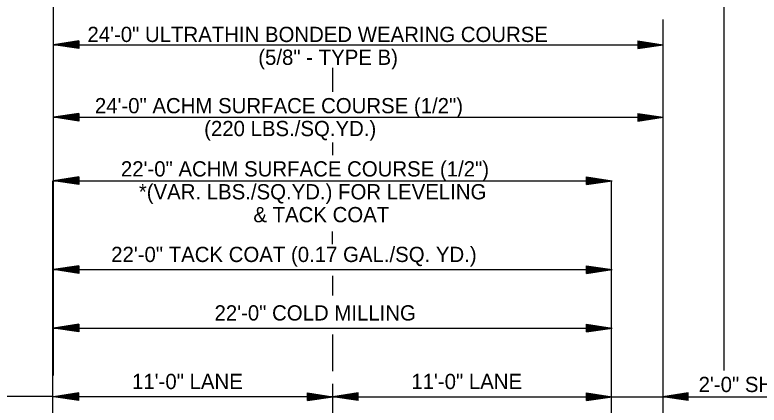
# Model space of a CAD drawing. Extents: x 2263886 to 2266026, y -3122850 to -3121850.
# Drawn here: x 2265384.71 to 2265414.02, y -3122478.48 to -3122463.12 of the extents above; entities that cross this region are included whole.
import ezdxf

# ---------------------------------------------------------------- set-up
doc = ezdxf.new("R2010")
doc.units = 0
doc.layers.add('R_Border Prem', color=7, linetype='Continuous')

msp = doc.modelspace()

# ---------------------------------------------------------------- linework, layer by layer
at = {"layer": 'R_Border Prem'}
for p, q in [((2265386.232, -3122477.321), (2265386.232, -3122460.397)), ((2265412.645, -3122477.115), (2265412.645, -3122460.346)), ((2265410.25, -3122482.649), (2265410.25, -3122463.3)), ((2265387.232, -3122464.15), (2265386.232, -3122464.3)), ((2265386.232, -3122464.3), (2265410.25, -3122464.3)), ((2265387.232, -3122464.45), (2265386.232, -3122464.3)), ((2265387.232, -3122464.175), (2265386.399, -3122464.3)), ((2265387.232, -3122464.425), (2265386.399, -3122464.3)), ((2265387.232, -3122464.201), (2265386.571, -3122464.3)), ((2265387.232, -3122464.4), (2265386.571, -3122464.3)), ((2265387.232, -3122464.226), (2265386.738, -3122464.3)), ((2265387.232, -3122464.375), (2265386.738, -3122464.3)), ((2265387.232, -3122464.252), (2265386.907, -3122464.3)), ((2265387.232, -3122464.349), (2265386.907, -3122464.3)), ((2265387.232, -3122464.277), (2265387.074, -3122464.3)), ((2265387.232, -3122464.324), (2265387.074, -3122464.3)), ((2265387.232, -3122464.15), (2265387.232, -3122464.45)), ((2265409.25, -3122464.15), (2265410.25, -3122464.3)), ((2265409.25, -3122464.15), (2265409.25, -3122464.45)), ((2265409.25, -3122464.175), (2265410.083, -3122464.3)), ((2265409.25, -3122464.201), (2265409.911, -3122464.3)), ((2265409.25, -3122464.226), (2265409.745, -3122464.3)), ((2265409.25, -3122464.252), (2265409.575, -3122464.3)), ((2265409.25, -3122464.277), (2265409.408, -3122464.3)), ((2265409.25, -3122464.45), (2265410.25, -3122464.3)), ((2265409.25, -3122464.349), (2265409.575, -3122464.3)), ((2265409.25, -3122464.4), (2265409.911, -3122464.3)), ((2265409.25, -3122464.425), (2265410.083, -3122464.3)), ((2265409.25, -3122464.375), (2265409.745, -3122464.3)), ((2265409.25, -3122464.324), (2265409.408, -3122464.3)), ((2265397.232, -3122466.149), (2265397.232, -3122465.205)), ((2265387.232, -3122466.999), (2265386.232, -3122467.149)), ((2265387.232, -3122467.024), (2265386.399, -3122467.149)), ((2265387.232, -3122466.999), (2265387.232, -3122467.299)), ((2265409.25, -3122466.999), (2265410.25, -3122467.149)), ((2265409.25, -3122466.999), (2265409.25, -3122467.299)), ((2265409.25, -3122467.024), (2265410.083, -3122467.149)), ((2265386.232, -3122467.149), (2265410.25, -3122467.149)), ((2265387.232, -3122467.299), (2265386.232, -3122467.149)), ((2265387.232, -3122467.274), (2265386.399, -3122467.149)), ((2265387.232, -3122467.05), (2265386.571, -3122467.149)), ((2265387.232, -3122467.249), (2265386.571, -3122467.149)), ((2265387.232, -3122467.075), (2265386.738, -3122467.149)), ((2265387.232, -3122467.224), (2265386.738, -3122467.149)), ((2265387.232, -3122467.101), (2265386.907, -3122467.149)), ((2265387.232, -3122467.198), (2265386.907, -3122467.149)), ((2265387.232, -3122467.126), (2265387.074, -3122467.149)), ((2265387.232, -3122467.173), (2265387.074, -3122467.149)), ((2265409.25, -3122467.05), (2265409.911, -3122467.149)), ((2265409.25, -3122467.075), (2265409.745, -3122467.149)), ((2265409.25, -3122467.101), (2265409.575, -3122467.149)), ((2265409.25, -3122467.126), (2265409.408, -3122467.149)), ((2265409.25, -3122467.299), (2265410.25, -3122467.149)), ((2265409.25, -3122467.198), (2265409.575, -3122467.149)), ((2265409.25, -3122467.249), (2265409.911, -3122467.149)), ((2265409.25, -3122467.274), (2265410.083, -3122467.149)), ((2265409.25, -3122467.224), (2265409.745, -3122467.149)), ((2265409.25, -3122467.173), (2265409.408, -3122467.149)), ((2265397.232, -3122468.649), (2265397.232, -3122468.149)), ((2265386.212, -3122469.649), (2265408.232, -3122469.649)), ((2265386.212, -3122482.649), (2265386.212, -3122469.649)), ((2265387.232, -3122469.499), (2265386.232, -3122469.649)), ((2265387.232, -3122469.799), (2265386.232, -3122469.649)), ((2265387.232, -3122469.524), (2265386.399, -3122469.649)), ((2265387.232, -3122469.774), (2265386.399, -3122469.649)), ((2265387.232, -3122469.55), (2265386.571, -3122469.649)), ((2265387.232, -3122469.749), (2265386.571, -3122469.649)), ((2265387.232, -3122469.575), (2265386.738, -3122469.649)), ((2265387.232, -3122469.724), (2265386.738, -3122469.649)), ((2265387.232, -3122469.601), (2265386.907, -3122469.649)), ((2265387.232, -3122469.698), (2265386.907, -3122469.649)), ((2265387.232, -3122469.626), (2265387.074, -3122469.649)), ((2265387.232, -3122469.673), (2265387.074, -3122469.649)), ((2265387.232, -3122469.499), (2265387.232, -3122469.799)), ((2265407.232, -3122469.499), (2265408.232, -3122469.649)), ((2265407.232, -3122469.799), (2265407.232, -3122469.499)), ((2265407.232, -3122469.524), (2265408.065, -3122469.649)), ((2265407.232, -3122469.55), (2265407.893, -3122469.649)), ((2265407.232, -3122469.575), (2265407.727, -3122469.649)), ((2265407.232, -3122469.6), (2265407.557, -3122469.649)), ((2265407.232, -3122469.626), (2265407.39, -3122469.649)), ((2265407.232, -3122469.799), (2265408.232, -3122469.649)), ((2265407.232, -3122469.698), (2265407.557, -3122469.649)), ((2265407.232, -3122469.749), (2265407.893, -3122469.649)), ((2265407.232, -3122469.774), (2265408.065, -3122469.649)), ((2265407.232, -3122469.724), (2265407.727, -3122469.649)), ((2265407.232, -3122469.673), (2265407.39, -3122469.649)), ((2265408.208, -3122482.649), (2265408.208, -3122469.649)), ((2265397.229, -3122472.149), (2265397.229, -3122471.649)), ((2265387.232, -3122472.999), (2265386.232, -3122473.149)), ((2265386.232, -3122473.149), (2265408.232, -3122473.149)), ((2265387.232, -3122473.299), (2265386.232, -3122473.149)), ((2265387.232, -3122473.024), (2265386.399, -3122473.149)), ((2265387.232, -3122473.274), (2265386.399, -3122473.149)), ((2265387.232, -3122473.05), (2265386.571, -3122473.149)), ((2265387.232, -3122473.249), (2265386.571, -3122473.149)), ((2265387.232, -3122473.075), (2265386.738, -3122473.149)), ((2265387.232, -3122473.224), (2265386.738, -3122473.149)), ((2265387.232, -3122473.101), (2265386.907, -3122473.149)), ((2265387.232, -3122473.198), (2265386.907, -3122473.149)), ((2265387.232, -3122473.126), (2265387.074, -3122473.149)), ((2265387.232, -3122473.173), (2265387.074, -3122473.149)), ((2265387.232, -3122472.999), (2265387.232, -3122473.299)), ((2265407.232, -3122472.999), (2265408.232, -3122473.149)), ((2265407.232, -3122473.299), (2265407.232, -3122472.999)), ((2265407.232, -3122473.024), (2265408.065, -3122473.149)), ((2265407.232, -3122473.05), (2265407.893, -3122473.149)), ((2265407.232, -3122473.075), (2265407.727, -3122473.149)), ((2265407.232, -3122473.1), (2265407.557, -3122473.149)), ((2265407.232, -3122473.126), (2265407.39, -3122473.149)), ((2265407.232, -3122473.299), (2265408.232, -3122473.149)), ((2265407.232, -3122473.198), (2265407.557, -3122473.149)), ((2265407.232, -3122473.249), (2265407.893, -3122473.149)), ((2265407.232, -3122473.274), (2265408.065, -3122473.149)), ((2265407.232, -3122473.224), (2265407.727, -3122473.149)), ((2265407.232, -3122473.173), (2265407.39, -3122473.149)), ((2265397.232, -3122474.166), (2265397.232, -3122473.399)), ((2265387.232, -3122475.301), (2265386.232, -3122475.451)), ((2265386.232, -3122475.451), (2265408.232, -3122475.451)), ((2265387.232, -3122475.601), (2265386.232, -3122475.451)), ((2265387.232, -3122475.326), (2265386.399, -3122475.451)), ((2265387.232, -3122475.576), (2265386.399, -3122475.451)), ((2265387.232, -3122475.351), (2265386.571, -3122475.451)), ((2265387.232, -3122475.55), (2265386.571, -3122475.451)), ((2265387.232, -3122475.376), (2265386.738, -3122475.451)), ((2265387.232, -3122475.525), (2265386.738, -3122475.451)), ((2265387.232, -3122475.402), (2265386.907, -3122475.451)), ((2265387.232, -3122475.5), (2265386.907, -3122475.451)), ((2265387.232, -3122475.427), (2265387.074, -3122475.451)), ((2265387.232, -3122475.474), (2265387.074, -3122475.451)), ((2265387.232, -3122475.301), (2265387.232, -3122475.601)), ((2265407.232, -3122475.301), (2265408.232, -3122475.451)), ((2265407.232, -3122475.601), (2265407.232, -3122475.301)), ((2265407.232, -3122475.326), (2265408.065, -3122475.451)), ((2265407.232, -3122475.351), (2265407.893, -3122475.451)), ((2265407.232, -3122475.376), (2265407.727, -3122475.451)), ((2265407.232, -3122475.402), (2265407.557, -3122475.451)), ((2265407.232, -3122475.427), (2265407.39, -3122475.451)), ((2265407.232, -3122475.601), (2265408.232, -3122475.451)), ((2265407.232, -3122475.499), (2265407.557, -3122475.451)), ((2265407.232, -3122475.55), (2265407.893, -3122475.451)), ((2265407.232, -3122475.576), (2265408.065, -3122475.451)), ((2265407.232, -3122475.525), (2265407.727, -3122475.451)), ((2265407.232, -3122475.474), (2265407.39, -3122475.451)), ((2265397.232, -3122477.149), (2265397.232, -3122475.699)), ((2265397.232, -3122482.649), (2265397.232, -3122477.649)), ((2265386.212, -3122478.146), (2265375.735, -3122478.146)), ((2265387.232, -3122477.999), (2265386.232, -3122478.149)), ((2265397.232, -3122478.149), (2265386.232, -3122478.149)), ((2265387.232, -3122478.299), (2265386.232, -3122478.149)), ((2265387.232, -3122478.024), (2265386.399, -3122478.149)), ((2265387.232, -3122478.274), (2265386.399, -3122478.149)), ((2265387.232, -3122478.05), (2265386.571, -3122478.149)), ((2265387.232, -3122478.249), (2265386.571, -3122478.149)), ((2265387.232, -3122478.075), (2265386.738, -3122478.149)), ((2265387.232, -3122478.224), (2265386.738, -3122478.149)), ((2265387.232, -3122478.1), (2265386.907, -3122478.149)), ((2265387.232, -3122478.198), (2265386.907, -3122478.149)), ((2265387.232, -3122478.126), (2265387.074, -3122478.149)), ((2265387.232, -3122478.173), (2265387.074, -3122478.149)), ((2265387.232, -3122478.299), (2265387.232, -3122477.999)), ((2265396.232, -3122477.999), (2265397.232, -3122478.149)), ((2265396.232, -3122478.299), (2265396.232, -3122477.999)), ((2265396.232, -3122478.024), (2265397.065, -3122478.149)), ((2265396.232, -3122478.05), (2265396.893, -3122478.149)), ((2265396.232, -3122478.075), (2265396.727, -3122478.149)), ((2265396.232, -3122478.1), (2265396.557, -3122478.149)), ((2265396.232, -3122478.126), (2265396.39, -3122478.149)), ((2265396.232, -3122478.299), (2265397.232, -3122478.149)), ((2265396.232, -3122478.198), (2265396.557, -3122478.149)), ((2265396.232, -3122478.249), (2265396.893, -3122478.149)), ((2265396.232, -3122478.274), (2265397.065, -3122478.149)), ((2265396.232, -3122478.224), (2265396.727, -3122478.149)), ((2265396.232, -3122478.173), (2265396.39, -3122478.149)), ((2265398.232, -3122477.999), (2265397.232, -3122478.149)), ((2265397.232, -3122478.149), (2265408.232, -3122478.149)), ((2265398.232, -3122478.299), (2265397.232, -3122478.149)), ((2265398.232, -3122478.024), (2265397.399, -3122478.149)), ((2265398.232, -3122478.274), (2265397.399, -3122478.149)), ((2265398.232, -3122478.05), (2265397.571, -3122478.149)), ((2265398.232, -3122478.249), (2265397.571, -3122478.149)), ((2265398.232, -3122478.075), (2265397.738, -3122478.149)), ((2265398.232, -3122478.224), (2265397.738, -3122478.149)), ((2265398.232, -3122478.1), (2265397.907, -3122478.149)), ((2265398.232, -3122478.198), (2265397.907, -3122478.149)), ((2265398.232, -3122478.126), (2265398.074, -3122478.149)), ((2265398.232, -3122478.173), (2265398.074, -3122478.149)), ((2265398.232, -3122478.299), (2265398.232, -3122477.999)), ((2265407.232, -3122477.999), (2265408.232, -3122478.149)), ((2265407.232, -3122478.299), (2265407.232, -3122477.999)), ((2265407.232, -3122478.024), (2265408.065, -3122478.149)), ((2265407.232, -3122478.05), (2265407.893, -3122478.149)), ((2265407.232, -3122478.075), (2265407.727, -3122478.149)), ((2265407.232, -3122478.1), (2265407.557, -3122478.149)), ((2265407.232, -3122478.126), (2265407.39, -3122478.149)), ((2265407.232, -3122478.299), (2265408.232, -3122478.149)), ((2265407.232, -3122478.198), (2265407.557, -3122478.149)), ((2265407.232, -3122478.249), (2265407.893, -3122478.149)), ((2265407.232, -3122478.274), (2265408.065, -3122478.149)), ((2265407.232, -3122478.224), (2265407.727, -3122478.149)), ((2265407.232, -3122478.173), (2265407.39, -3122478.149)), ((2265408.232, -3122478.149), (2265417.137, -3122478.149)), ((2265411.232, -3122477.999), (2265410.232, -3122478.149)), ((2265411.232, -3122478.299), (2265410.232, -3122478.149)), ((2265411.232, -3122478.024), (2265410.399, -3122478.149)), ((2265411.232, -3122478.274), (2265410.399, -3122478.149)), ((2265411.232, -3122478.05), (2265410.571, -3122478.149)), ((2265411.232, -3122478.249), (2265410.571, -3122478.149)), ((2265411.232, -3122478.075), (2265410.738, -3122478.149)), ((2265411.232, -3122478.224), (2265410.738, -3122478.149)), ((2265411.232, -3122478.1), (2265410.907, -3122478.149)), ((2265411.232, -3122478.198), (2265410.907, -3122478.149)), ((2265411.232, -3122478.126), (2265411.074, -3122478.149)), ((2265411.232, -3122478.173), (2265411.074, -3122478.149)), ((2265411.232, -3122478.299), (2265411.232, -3122477.999))]:
    msp.add_line(p, q, dxfattribs=at)

# ---------------------------------------------------------------- texts
for s, p in [('24\'-0" ULTRATHIN BONDED WEARING COURSE', (2265387.571, -3122464.19)), ('(5/8" - TYPE B)', (2265394.299, -3122465.09)), ('24\'-0" ACHM SURFACE COURSE (1/2")', (2265387.864, -3122466.995)), ('(220 LBS./SQ.YD.)', (2265392.168, -3122467.895)), ('22\'-0" ACHM SURFACE COURSE (1/2")', (2265388.889, -3122469.483)), ('*(VAR. LBS./SQ.YD.) FOR LEVELING', (2265389.595, -3122470.383)), ('& TACK COAT', (2265394.107, -3122471.283)), ('22\'-0" TACK COAT (0.17 GAL./SQ. YD.)', (2265388.506, -3122472.849)), ('22\'-0" COLD MILLING', (2265392.576, -3122475.151))]:
    msp.add_text(s, height=0.6, rotation=360, dxfattribs=at).set_placement(p)
for s, p in [('11\'-0" LANE', (2265389.327, -3122477.849)), ('11\'-0" LANE', (2265400.327, -3122477.849)), ('2\'-0" SHLD.', (2265411.643, -3122477.967))]:
    msp.add_text(s, height=0.6, dxfattribs=at).set_placement(p)

doc.saveas('drawing.dxf')
